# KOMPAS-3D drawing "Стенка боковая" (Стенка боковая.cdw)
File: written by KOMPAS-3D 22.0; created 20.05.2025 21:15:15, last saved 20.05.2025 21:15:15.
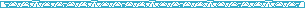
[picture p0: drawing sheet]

Sheet 1: A4, portrait

Document properties: Автор: user; Масса: 11.51708; Полное имя файла: Стенка боковая.m3d

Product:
- Part/product: Стенка боковая
    Масса: 11.51708
- Part/product: Стенка боковая  | designation 01
    Масса: 17.009285

Title block, sheet 1: Наименование: Стенка боковая; Материал: Сталь 10 ГОСТ 1050-2013; Масса: 11,52; Количество листов документа: 1; Форматы листов документа: A4

Referenced files in D:\Работа\2025\5. Май\Задание №6 - Тележка для крыши\3Д\Тележка в сборе\Корпус тележки\: Стенка боковая.m3d
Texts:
  Без оформления
Dimensions and other numbers on the sheet: 1:1; 1; 11,52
